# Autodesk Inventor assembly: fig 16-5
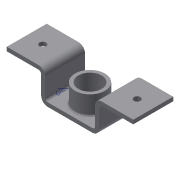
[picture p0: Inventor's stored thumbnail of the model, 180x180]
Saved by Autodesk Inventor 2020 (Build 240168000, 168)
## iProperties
Created: 2004-07
Part Number: fig 16-5
Document SubType Name: Weldment
Designer: CADCIM Technologies
Manufacturer: Standard
Standards Organization: Custom
Author: CADCIM Technologies
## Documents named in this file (3)
- D:\Autodesk Inventor_2020\Resources\Resources\Inventor_2020_Part\Inventor_2020_Part\c16_Inv_2020_prt\fig 16-5\fig 16-5.iam
- D:\Autodesk Inventor_2020\Resources\Resources\Inventor_2020_Part\Inventor_2020_Part\c16_Inv_2020_prt\fig 16-5\Bracket.ipt
- D:\Autodesk Inventor_2020\Resources\Resources\Inventor_2020_Part\Inventor_2020_Part\c16_Inv_2020_prt\fig 16-5\cylinder.ipt
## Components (2 placed, 2 different names)
1. Bracket:1 — Insert:1
2. cylinder:1 — Insert:1
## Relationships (1: Insert 1)
- Insert:1: Bracket:1 ↔ cylinder:1
